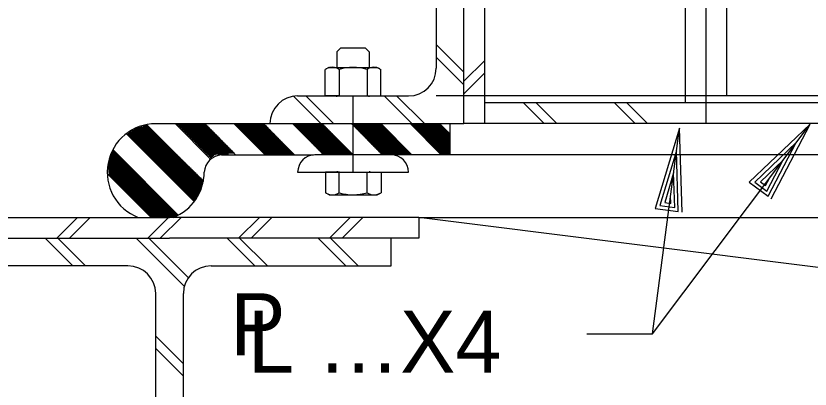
# Model space of a CAD drawing. Extents: x 4.9 to 31.6, y 3.9 to 22.6.
# Drawn here: x 26.163 to 27.357, y 15.318 to 15.879 of the extents above; entities that cross this region are included whole.
import ezdxf

# ---------------------------------------------------------------- set-up
doc = ezdxf.new("R2010")
doc.units = 0
for name, color, linetype in [('Level 2', 7, 'Continuous'), ('Level 25', 7, 'Continuous'), ('Level 3', 7, 'Continuous'), ('Level 50', 7, 'Continuous')]:
    doc.layers.add(name, color=color, linetype=linetype)

msp = doc.modelspace()

# ---------------------------------------------------------------- linework, layer by layer
at = {"layer": 'Level 2'}
for p, q in [((27.2319, 15.7584), (27.2319, 20.9561)), ((26.8364, 15.7168), (26.8364, 17.0205)), ((26.8677, 15.7168), (26.8677, 17.0205)), ((27.1697, 15.748), (27.1697, 16.5655)), ((27.201, 15.7168), (27.201, 16.5655)), ((26.7947, 16.0918), (26.7947, 15.8001)), ((26.6455, 15.8249), (26.6515, 15.8309)), ((26.6515, 15.8309), (26.6879, 15.8309)), ((26.694, 15.8249), (26.6879, 15.8309)), ((26.6455, 15.8249), (26.6455, 15.8014)), ((26.694, 15.8249), (26.694, 15.8014)), ((26.6334, 15.8014), (26.6279, 15.7982)), ((26.6279, 15.7584), (26.6279, 15.7982)), ((26.6334, 15.8014), (26.706, 15.8014)), ((26.6487, 15.7983), (26.6487, 15.7584)), ((26.6907, 15.7983), (26.6907, 15.7584)), ((26.706, 15.8014), (26.7116, 15.7982)), ((26.7116, 15.7584), (26.7116, 15.7982)), ((26.5864, 15.7584), (26.7531, 15.7584)), ((26.6279, 15.7584), (26.7116, 15.7584)), ((26.649, 15.7584), (26.6279, 15.7584)), ((26.6455, 15.7569), (26.6455, 15.7584)), ((26.6697, 15.6438), (26.6697, 15.7584)), ((26.694, 15.7569), (26.694, 15.7584)), ((27.8887, 15.7584), (26.7947, 15.7584)), ((27.409, 15.748), (26.8677, 15.748)), ((26.9573, 15.7168), (26.926, 15.748)), ((26.9761, 15.7168), (26.9449, 15.748)), ((27.094, 15.7168), (27.0627, 15.748)), ((27.1128, 15.7168), (27.0816, 15.748)), ((26.3655, 15.708), (26.3403, 15.708)), ((26.3642, 15.7092), (26.3422, 15.7092)), ((26.3629, 15.7105), (26.3456, 15.7105)), ((26.3617, 15.7117), (26.3499, 15.7117)), ((26.3604, 15.713), (26.3542, 15.713)), ((26.3591, 15.7142), (26.3586, 15.7142)), ((26.4445, 15.6301), (26.3591, 15.7154)), ((26.3729, 15.7168), (26.8156, 15.7168)), ((26.4555, 15.6632), (26.402, 15.7168)), ((26.4479, 15.7161), (26.4045, 15.7161)), ((26.4492, 15.7149), (26.4057, 15.7149)), ((26.4504, 15.7136), (26.407, 15.7136)), ((26.4517, 15.7124), (26.4082, 15.7124)), ((26.4529, 15.7111), (26.4095, 15.7111)), ((26.4542, 15.7099), (26.4107, 15.7099)), ((26.4554, 15.7086), (26.412, 15.7086)), ((26.4931, 15.6699), (26.4462, 15.7168)), ((26.5373, 15.6699), (26.4904, 15.7168)), ((26.5365, 15.7162), (26.4909, 15.7162)), ((26.5377, 15.7149), (26.4922, 15.7149)), ((26.5389, 15.7137), (26.4934, 15.7137)), ((26.5401, 15.7124), (26.4946, 15.7124)), ((26.5413, 15.7112), (26.4959, 15.7112)), ((26.5425, 15.7099), (26.4971, 15.7099)), ((26.5437, 15.7087), (26.4983, 15.7087)), ((26.5814, 15.6699), (26.5346, 15.7168)), ((26.6256, 15.6699), (26.5788, 15.7168)), ((26.6252, 15.715), (26.5806, 15.715)), ((26.6264, 15.7138), (26.5819, 15.7138)), ((26.6277, 15.7125), (26.5831, 15.7125)), ((26.6289, 15.7113), (26.5843, 15.7113)), ((26.6301, 15.71), (26.5855, 15.71)), ((26.6313, 15.7088), (26.5867, 15.7088)), ((26.624, 15.7163), (26.6098, 15.7163)), ((26.6698, 15.6699), (26.623, 15.7168)), ((26.714, 15.6699), (26.6672, 15.7168)), ((26.7122, 15.7155), (26.6681, 15.7155)), ((26.7134, 15.7143), (26.6693, 15.7143)), ((26.7147, 15.713), (26.6705, 15.713)), ((26.7159, 15.7118), (26.6717, 15.7118)), ((26.7172, 15.7105), (26.673, 15.7105)), ((26.7184, 15.7093), (26.6742, 15.7093)), ((26.7197, 15.708), (26.6754, 15.708)), ((26.7582, 15.6699), (26.7113, 15.7168)), ((26.8024, 15.6699), (26.7556, 15.7168)), ((26.8008, 15.7152), (26.7573, 15.7152)), ((26.8022, 15.714), (26.7586, 15.714)), ((26.8035, 15.7127), (26.7598, 15.7127)), ((26.8049, 15.7115), (26.7611, 15.7115)), ((26.8063, 15.7102), (26.7623, 15.7102)), ((26.8077, 15.709), (26.7636, 15.709)), ((26.8156, 15.7009), (26.7997, 15.7168)), ((26.8156, 15.6699), (26.8156, 15.7168)), ((26.8156, 15.7168), (26.8364, 15.7168)), ((27.201, 15.7168), (26.8364, 15.7168)), ((27.409, 15.7168), (27.201, 15.7168)), ((26.4308, 15.5996), (26.3286, 15.7018)), ((26.3719, 15.7017), (26.331, 15.7017)), ((26.3732, 15.7005), (26.3312, 15.7005)), ((26.3745, 15.6992), (26.3324, 15.6992)), ((26.3707, 15.703), (26.3329, 15.703)), ((26.3758, 15.698), (26.3337, 15.698)), ((26.3694, 15.7042), (26.3347, 15.7042)), ((26.3771, 15.6967), (26.3349, 15.6967)), ((26.3681, 15.7055), (26.3366, 15.7055)), ((26.3668, 15.7067), (26.3384, 15.7067)), ((26.4566, 15.7074), (26.4132, 15.7074)), ((26.4579, 15.7061), (26.4145, 15.7061)), ((26.4591, 15.7049), (26.4157, 15.7049)), ((26.4604, 15.7036), (26.417, 15.7036)), ((26.4616, 15.7024), (26.4183, 15.7024)), ((26.4629, 15.7011), (26.4195, 15.7011)), ((26.4641, 15.6999), (26.4208, 15.6999)), ((26.4653, 15.6986), (26.422, 15.6986)), ((26.4666, 15.6974), (26.4233, 15.6974)), ((26.4678, 15.6961), (26.4245, 15.6961)), ((26.5449, 15.7074), (26.4996, 15.7074)), ((26.5461, 15.7062), (26.5008, 15.7062)), ((26.5473, 15.7049), (26.5021, 15.7049)), ((26.5485, 15.7037), (26.5033, 15.7037)), ((26.5497, 15.7024), (26.5045, 15.7024)), ((26.5509, 15.7012), (26.5058, 15.7012)), ((26.5521, 15.6999), (26.507, 15.6999)), ((26.5533, 15.6987), (26.5082, 15.6987)), ((26.5545, 15.6974), (26.5095, 15.6974)), ((26.5557, 15.6962), (26.5107, 15.6962)), ((26.6325, 15.7075), (26.5879, 15.7075)), ((26.6337, 15.7063), (26.5892, 15.7063)), ((26.6349, 15.705), (26.5904, 15.705)), ((26.6362, 15.7038), (26.5916, 15.7038)), ((26.6374, 15.7025), (26.5928, 15.7025)), ((26.6386, 15.7013), (26.594, 15.7013)), ((26.6398, 15.7), (26.5952, 15.7)), ((26.641, 15.6988), (26.5965, 15.6988)), ((26.6422, 15.6975), (26.5977, 15.6975)), ((26.6434, 15.6963), (26.5989, 15.6963)), ((26.7209, 15.7068), (26.6767, 15.7068)), ((26.7222, 15.7055), (26.6779, 15.7055)), ((26.7234, 15.7043), (26.6791, 15.7043)), ((26.7247, 15.703), (26.6804, 15.703)), ((26.726, 15.7018), (26.6816, 15.7018)), ((26.7272, 15.7005), (26.6828, 15.7005)), ((26.7285, 15.6993), (26.6841, 15.6993)), ((26.7297, 15.698), (26.6853, 15.698)), ((26.731, 15.6968), (26.6865, 15.6968)), ((26.809, 15.7077), (26.7648, 15.7077)), ((26.8104, 15.7065), (26.7661, 15.7065)), ((26.8118, 15.7052), (26.7673, 15.7052)), ((26.8132, 15.704), (26.7686, 15.704)), ((26.8145, 15.7027), (26.7698, 15.7027)), ((26.8153, 15.7015), (26.7711, 15.7015)), ((26.8153, 15.7002), (26.7723, 15.7002)), ((26.8153, 15.699), (26.7736, 15.699)), ((26.8154, 15.6977), (26.7748, 15.6977)), ((26.8154, 15.6965), (26.7761, 15.6965)), ((26.3784, 15.6955), (26.3362, 15.6955)), ((26.3797, 15.6942), (26.3374, 15.6942)), ((26.381, 15.693), (26.3387, 15.693)), ((26.3823, 15.6917), (26.3399, 15.6917)), ((26.3836, 15.6905), (26.3412, 15.6905)), ((26.3849, 15.6892), (26.3424, 15.6892)), ((26.3862, 15.688), (26.3437, 15.688)), ((26.3874, 15.6867), (26.3449, 15.6867)), ((26.3887, 15.6855), (26.3462, 15.6855)), ((26.39, 15.6842), (26.3474, 15.6842)), ((26.4691, 15.6949), (26.4258, 15.6949)), ((26.4703, 15.6936), (26.427, 15.6936)), ((26.4716, 15.6924), (26.4283, 15.6924)), ((26.4728, 15.6911), (26.4295, 15.6911)), ((26.4741, 15.6899), (26.4308, 15.6899)), ((26.4753, 15.6886), (26.432, 15.6886)), ((26.4765, 15.6874), (26.4333, 15.6874)), ((26.4778, 15.6861), (26.4345, 15.6861)), ((26.479, 15.6849), (26.4358, 15.6849)), ((26.5569, 15.6949), (26.512, 15.6949)), ((26.5581, 15.6937), (26.5132, 15.6937)), ((26.5593, 15.6924), (26.5144, 15.6924)), ((26.5605, 15.6912), (26.5157, 15.6912)), ((26.5617, 15.6899), (26.5169, 15.6899)), ((26.5629, 15.6887), (26.5182, 15.6887)), ((26.5641, 15.6874), (26.5194, 15.6874)), ((26.5653, 15.6862), (26.5207, 15.6862)), ((26.5665, 15.6849), (26.5219, 15.6849)), ((26.6447, 15.695), (26.6001, 15.695)), ((26.6459, 15.6938), (26.6013, 15.6938)), ((26.6471, 15.6925), (26.6026, 15.6925)), ((26.6483, 15.6913), (26.6038, 15.6913)), ((26.6495, 15.69), (26.605, 15.69)), ((26.6507, 15.6888), (26.6062, 15.6888)), ((26.6519, 15.6875), (26.6074, 15.6875)), ((26.6532, 15.6863), (26.6087, 15.6863)), ((26.6544, 15.685), (26.6099, 15.685)), ((26.7323, 15.6955), (26.6878, 15.6955)), ((26.7335, 15.6943), (26.689, 15.6943)), ((26.7348, 15.693), (26.6902, 15.693)), ((26.736, 15.6918), (26.6915, 15.6918)), ((26.7373, 15.6905), (26.6927, 15.6905)), ((26.7386, 15.6893), (26.6939, 15.6893)), ((26.7398, 15.688), (26.6952, 15.688)), ((26.7411, 15.6868), (26.6964, 15.6868)), ((26.7423, 15.6855), (26.6976, 15.6855)), ((26.7436, 15.6843), (26.6989, 15.6843)), ((26.8154, 15.6952), (26.7773, 15.6952)), ((26.8154, 15.694), (26.7786, 15.694)), ((26.8154, 15.6927), (26.7798, 15.6927)), ((26.8155, 15.6915), (26.7811, 15.6915)), ((26.8155, 15.6902), (26.7823, 15.6902)), ((26.8155, 15.689), (26.7836, 15.689)), ((26.8155, 15.6877), (26.7848, 15.6877)), ((26.8156, 15.6865), (26.7861, 15.6865)), ((26.8156, 15.6852), (26.7873, 15.6852)), ((26.8156, 15.684), (26.7886, 15.684)), ((26.3129, 15.6724), (26.3071, 15.6724)), ((26.3116, 15.6736), (26.3077, 15.6736)), ((26.4068, 15.5793), (26.3083, 15.6778)), ((26.3103, 15.6749), (26.3084, 15.6749)), ((26.3913, 15.683), (26.3487, 15.683)), ((26.3926, 15.6817), (26.3499, 15.6817)), ((26.3939, 15.6805), (26.3511, 15.6805)), ((26.3952, 15.6792), (26.3524, 15.6792)), ((26.3964, 15.678), (26.3536, 15.678)), ((26.3977, 15.6767), (26.3549, 15.6767)), ((26.399, 15.6755), (26.3561, 15.6755)), ((26.4003, 15.6742), (26.3574, 15.6742)), ((26.4016, 15.673), (26.3586, 15.673)), ((26.4803, 15.6836), (26.437, 15.6836)), ((26.4815, 15.6824), (26.4383, 15.6824)), ((26.4828, 15.6811), (26.4395, 15.6811)), ((26.484, 15.6799), (26.4408, 15.6799)), ((26.4852, 15.6786), (26.442, 15.6786)), ((26.4865, 15.6774), (26.4433, 15.6774)), ((26.4877, 15.6761), (26.4445, 15.6761)), ((26.489, 15.6749), (26.4458, 15.6749)), ((26.4902, 15.6736), (26.447, 15.6736)), ((26.4915, 15.6724), (26.4483, 15.6724)), ((26.5677, 15.6837), (26.5231, 15.6837)), ((26.5689, 15.6824), (26.5244, 15.6824)), ((26.5701, 15.6812), (26.5256, 15.6812)), ((26.5713, 15.6799), (26.5268, 15.6799)), ((26.5725, 15.6787), (26.5281, 15.6787)), ((26.5737, 15.6774), (26.5293, 15.6774)), ((26.5749, 15.6762), (26.5306, 15.6762)), ((26.5761, 15.6749), (26.5318, 15.6749)), ((26.5773, 15.6737), (26.533, 15.6737)), ((26.5785, 15.6724), (26.5343, 15.6724)), ((26.6556, 15.6838), (26.6111, 15.6838)), ((26.6568, 15.6825), (26.6123, 15.6825)), ((26.658, 15.6813), (26.6135, 15.6813)), ((26.6592, 15.68), (26.6147, 15.68)), ((26.6604, 15.6788), (26.6159, 15.6788)), ((26.6617, 15.6775), (26.6172, 15.6775)), ((26.6629, 15.6763), (26.6184, 15.6763)), ((26.6641, 15.675), (26.6196, 15.675)), ((26.6653, 15.6738), (26.6208, 15.6738)), ((26.6665, 15.6725), (26.622, 15.6725)), ((26.7448, 15.683), (26.7001, 15.683)), ((26.7461, 15.6818), (26.7013, 15.6818)), ((26.7474, 15.6805), (26.7026, 15.6805)), ((26.7486, 15.6793), (26.7038, 15.6793)), ((26.7499, 15.678), (26.705, 15.678)), ((26.7511, 15.6768), (26.7063, 15.6768)), ((26.7524, 15.6755), (26.7075, 15.6755)), ((26.7537, 15.6743), (26.7087, 15.6743)), ((26.7549, 15.673), (26.7099, 15.673)), ((26.8156, 15.6827), (26.7898, 15.6827)), ((26.8157, 15.6815), (26.7911, 15.6815)), ((26.8157, 15.6802), (26.7923, 15.6802)), ((26.8157, 15.679), (26.7936, 15.679)), ((26.8157, 15.6777), (26.7948, 15.6777)), ((26.8157, 15.6765), (26.7961, 15.6765)), ((26.8157, 15.6752), (26.7974, 15.6752)), ((26.8158, 15.674), (26.7986, 15.674)), ((26.8158, 15.6727), (26.7999, 15.6727)), ((26.3242, 15.6611), (26.3028, 15.6611)), ((26.3229, 15.6624), (26.303, 15.6624)), ((26.3217, 15.6636), (26.3033, 15.6636)), ((26.3204, 15.6649), (26.3036, 15.6649)), ((26.3192, 15.6661), (26.3038, 15.6661)), ((26.3179, 15.6674), (26.3043, 15.6674)), ((26.3167, 15.6686), (26.305, 15.6686)), ((26.3154, 15.6699), (26.3057, 15.6699)), ((26.3141, 15.6711), (26.3064, 15.6711)), ((26.4029, 15.6717), (26.3599, 15.6717)), ((26.4042, 15.6705), (26.3611, 15.6705)), ((26.4055, 15.6692), (26.3624, 15.6692)), ((26.4068, 15.668), (26.3636, 15.668)), ((26.4081, 15.6667), (26.3649, 15.6667)), ((26.4093, 15.6655), (26.3661, 15.6655)), ((26.4106, 15.6642), (26.3674, 15.6642)), ((26.4119, 15.663), (26.3686, 15.663)), ((26.4132, 15.6617), (26.3698, 15.6617)), ((26.4145, 15.6605), (26.3711, 15.6605)), ((26.4824, 15.6711), (26.4495, 15.6711)), ((26.4629, 15.6699), (26.4508, 15.6699)), ((26.4603, 15.6686), (26.4521, 15.6686)), ((26.4587, 15.6674), (26.4533, 15.6674)), ((26.4572, 15.6661), (26.4546, 15.6661)), ((26.4721, 15.6699), (26.6103, 15.6699)), ((26.5797, 15.6712), (26.5355, 15.6712)), ((26.5521, 15.6699), (26.5367, 15.6699)), ((26.8156, 15.6699), (26.6124, 15.6699)), ((26.6677, 15.6713), (26.6233, 15.6713)), ((26.6689, 15.67), (26.6245, 15.67)), ((26.7562, 15.6718), (26.7112, 15.6718)), ((26.7574, 15.6705), (26.7124, 15.6705)), ((26.8158, 15.6715), (26.8011, 15.6715)), ((27.4822, 15.6699), (26.8156, 15.6699)), ((26.333, 15.6524), (26.3011, 15.6524)), ((26.3318, 15.6536), (26.3012, 15.6536)), ((26.3343, 15.6511), (26.3012, 15.6511)), ((26.3355, 15.6499), (26.3014, 15.6499)), ((26.3305, 15.6549), (26.3015, 15.6549)), ((26.3368, 15.6486), (26.3015, 15.6486)), ((26.3292, 15.6561), (26.3017, 15.6561)), ((26.328, 15.6574), (26.302, 15.6574)), ((26.3267, 15.6586), (26.3023, 15.6586)), ((26.3255, 15.6599), (26.3025, 15.6599)), ((26.4158, 15.6592), (26.3723, 15.6592)), ((26.4171, 15.658), (26.3736, 15.658)), ((26.4184, 15.6567), (26.3748, 15.6567)), ((26.4197, 15.6555), (26.3761, 15.6555)), ((26.4209, 15.6542), (26.3773, 15.6542)), ((26.4222, 15.653), (26.3786, 15.653)), ((26.4235, 15.6517), (26.3798, 15.6517)), ((26.4248, 15.6505), (26.3811, 15.6505)), ((26.4261, 15.6492), (26.3823, 15.6492)), ((26.3661, 15.5759), (26.2999, 15.642)), ((26.3381, 15.6474), (26.3017, 15.6474)), ((26.3393, 15.6461), (26.3018, 15.6461)), ((26.3406, 15.6449), (26.3019, 15.6449)), ((26.3418, 15.6436), (26.3021, 15.6436)), ((26.3431, 15.6424), (26.3022, 15.6424)), ((26.3444, 15.6411), (26.3024, 15.6411)), ((26.3456, 15.6399), (26.3025, 15.6399)), ((26.3469, 15.6386), (26.3037, 15.6386)), ((26.3482, 15.6374), (26.3049, 15.6374)), ((26.3494, 15.6361), (26.3062, 15.6361)), ((26.4274, 15.648), (26.3836, 15.648)), ((26.4287, 15.6467), (26.3848, 15.6467)), ((26.43, 15.6455), (26.3861, 15.6455)), ((26.4313, 15.6442), (26.3873, 15.6442)), ((26.4326, 15.643), (26.3886, 15.643)), ((26.4338, 15.6417), (26.3898, 15.6417)), ((26.4351, 15.6405), (26.3911, 15.6405)), ((26.4364, 15.6392), (26.3923, 15.6392)), ((26.4377, 15.638), (26.3935, 15.638)), ((26.439, 15.6367), (26.3948, 15.6367)), ((26.5864, 15.6438), (26.7531, 15.6438)), ((26.5864, 15.6438), (26.6207, 15.6438)), ((26.6281, 15.6437), (26.7118, 15.6437)), ((26.6493, 15.6437), (26.6281, 15.6437)), ((26.6281, 15.6437), (26.6281, 15.613)), ((26.6457, 15.6452), (26.6457, 15.6437)), ((26.649, 15.6129), (26.649, 15.6437)), ((26.6909, 15.6129), (26.6909, 15.6437)), ((26.6942, 15.6452), (26.6942, 15.6437)), ((26.7118, 15.6437), (26.7118, 15.613)), ((26.3507, 15.6349), (26.3074, 15.6349)), ((26.3519, 15.6336), (26.3087, 15.6336)), ((26.3532, 15.6324), (26.3099, 15.6324)), ((26.3544, 15.6311), (26.3112, 15.6311)), ((26.3557, 15.6299), (26.3124, 15.6299)), ((26.357, 15.6286), (26.3137, 15.6286)), ((26.3582, 15.6274), (26.315, 15.6274)), ((26.3595, 15.6261), (26.3162, 15.6261)), ((26.3607, 15.6249), (26.3175, 15.6249)), ((26.4403, 15.6355), (26.396, 15.6355)), ((26.4416, 15.6342), (26.3973, 15.6342)), ((26.4429, 15.633), (26.3985, 15.633)), ((26.4442, 15.6317), (26.3998, 15.6317)), ((26.4454, 15.6305), (26.401, 15.6305)), ((26.4449, 15.6292), (26.4023, 15.6292)), ((26.4445, 15.628), (26.4035, 15.628)), ((26.444, 15.6267), (26.4048, 15.6267)), ((26.4435, 15.6255), (26.406, 15.6255)), ((26.443, 15.6242), (26.4073, 15.6242)), ((26.362, 15.6236), (26.3187, 15.6236)), ((26.3633, 15.6224), (26.32, 15.6224)), ((26.3645, 15.6211), (26.3213, 15.6211)), ((26.3658, 15.6199), (26.3225, 15.6199)), ((26.3671, 15.6186), (26.3238, 15.6186)), ((26.3683, 15.6174), (26.325, 15.6174)), ((26.3696, 15.6161), (26.3263, 15.6161)), ((26.3708, 15.6149), (26.3276, 15.6149)), ((26.3721, 15.6136), (26.3288, 15.6136)), ((26.3734, 15.6124), (26.3301, 15.6124)), ((26.4425, 15.623), (26.4085, 15.623)), ((26.442, 15.6217), (26.4098, 15.6217)), ((26.4415, 15.6205), (26.411, 15.6205)), ((26.441, 15.6192), (26.4122, 15.6192)), ((26.4405, 15.618), (26.4135, 15.618)), ((26.44, 15.6167), (26.4147, 15.6167)), ((26.4395, 15.6155), (26.416, 15.6155)), ((26.4388, 15.6142), (26.4172, 15.6142)), ((26.4381, 15.613), (26.4185, 15.613)), ((26.6337, 15.6097), (26.6281, 15.613)), ((26.7062, 15.6097), (26.7118, 15.613)), ((26.3746, 15.6111), (26.3313, 15.6111)), ((26.3759, 15.6099), (26.3326, 15.6099)), ((26.3771, 15.6086), (26.3338, 15.6086)), ((26.3784, 15.6074), (26.3351, 15.6074)), ((26.3797, 15.6061), (26.3364, 15.6061)), ((26.3809, 15.6049), (26.3376, 15.6049)), ((26.3822, 15.6036), (26.3389, 15.6036)), ((26.3834, 15.6024), (26.3401, 15.6024)), ((26.3847, 15.6011), (26.3414, 15.6011)), ((26.4373, 15.6117), (26.4197, 15.6117)), ((26.4366, 15.6105), (26.421, 15.6105)), ((26.4358, 15.6092), (26.4222, 15.6092)), ((26.4351, 15.608), (26.4235, 15.608)), ((26.4344, 15.6067), (26.4247, 15.6067)), ((26.4336, 15.6055), (26.426, 15.6055)), ((26.4329, 15.6042), (26.4272, 15.6042)), ((26.4322, 15.603), (26.4285, 15.603)), ((26.4314, 15.6017), (26.4297, 15.6017)), ((26.6337, 15.6097), (26.7062, 15.6097)), ((26.3859, 15.5999), (26.3427, 15.5999)), ((26.3872, 15.5986), (26.3439, 15.5986)), ((26.3885, 15.5974), (26.3452, 15.5974)), ((26.3897, 15.5961), (26.3464, 15.5961)), ((26.3909, 15.5944), (26.3476, 15.5944)), ((26.3922, 15.5932), (26.3489, 15.5932)), ((26.3934, 15.5919), (26.3501, 15.5919)), ((26.3947, 15.5907), (26.3514, 15.5907)), ((26.3959, 15.5894), (26.3526, 15.5894)), ((26.3972, 15.5882), (26.3539, 15.5882)), ((26.3985, 15.5869), (26.3552, 15.5869)), ((26.3997, 15.5857), (26.3564, 15.5857)), ((26.401, 15.5844), (26.3577, 15.5844)), ((26.4022, 15.5832), (26.3589, 15.5832)), ((26.4035, 15.5819), (26.3602, 15.5819)), ((26.4048, 15.5807), (26.3614, 15.5807)), ((26.4053, 15.5794), (26.3627, 15.5794)), ((26.403, 15.5782), (26.3639, 15.5782)), ((26.402, 15.577), (26.3649, 15.577)), ((26.0187, 15.5759), (26.3937, 15.5759)), ((26.2242, 15.5446), (26.2554, 15.5759)), ((26.243, 15.5446), (26.2743, 15.5759)), ((26.3609, 15.5446), (26.3921, 15.5759)), ((26.3797, 15.5446), (26.411, 15.5759)), ((26.7687, 15.5759), (26.3937, 15.5759)), ((26.4976, 15.5446), (26.5288, 15.5759)), ((26.5164, 15.5446), (26.5477, 15.5759)), ((26.6343, 15.5446), (26.6656, 15.5759)), ((26.6532, 15.5446), (26.6844, 15.5759)), ((26.7687, 15.5759), (26.7687, 15.5446)), ((26.7687, 15.5759), (27.4822, 15.5759)), ((27.4302, 15.4926), (26.7687, 15.5759)), ((26.0187, 15.5446), (26.3937, 15.5446)), ((26.2485, 15.503), (26.2068, 15.5446)), ((26.2674, 15.503), (26.2257, 15.5446)), ((26.416, 15.4722), (26.3436, 15.5446)), ((26.422, 15.4851), (26.3624, 15.5446)), ((26.7687, 15.5446), (26.3937, 15.5446)), ((26.5219, 15.503), (26.4803, 15.5446)), ((26.5408, 15.503), (26.4991, 15.5446)), ((26.6586, 15.503), (26.617, 15.5446)), ((26.6775, 15.503), (26.6358, 15.5446)), ((26.727, 15.503), (26.727, 15.5446)), ((26.3312, 15.503), (26.0604, 15.503)), ((26.4562, 15.503), (26.727, 15.503)), ((26.3729, 15.1044), (26.3729, 15.4613)), ((26.4145, 15.1044), (26.4145, 15.4613)), ((26.4145, 15.3558), (26.3729, 15.3975)), ((26.4145, 15.337), (26.3729, 15.3786))]:
    msp.add_line(p, q, dxfattribs=at)
for centre, radius, start, end in [((26.6385, 15.7833), 0.0182, 55.489, 120.2876), ((26.6695, 15.7287), 0.0727, 73.0184, 106.4966), ((26.701, 15.7833), 0.0182, 59.7124, 124.511), ((26.7531, 15.8001), 0.0417, 270, 0), ((26.5864, 15.7168), 0.0417, 90, 180), ((26.3729, 15.6438), 0.0729, 90, 248.7036), ((26.4736, 15.642), 0.0279, 93.1528, 176.2998), ((26.6124, 15.6438), 0.026, 90, 180), ((26.727, 15.6438), 0.026, 0, 90), ((26.3729, 15.6438), 0.0729, 291.2964, 0), ((26.6387, 15.6279), 0.0182, 239.7124, 304.511), ((26.6697, 15.6825), 0.0727, 253.5034, 286.9816), ((26.7012, 15.6279), 0.0182, 235.489, 300.2876), ((26.3312, 15.4613), 0.0417, 0, 90), ((26.4562, 15.4613), 0.0417, 90, 180)]:
    msp.add_arc(centre, radius, start, end, dxfattribs=at)
at = {"layer": 'Level 25'}
msp.add_line((27.1201, 15.4008), (27.357, 15.716), dxfattribs=at)
at = {"layer": 'Level 3'}
for p, q in [((26.8364, 15.7941), (26.7947, 15.8357)), ((26.8364, 15.7752), (26.7947, 15.8169)), ((26.8364, 15.7805), (26.8677, 15.8118)), ((26.8364, 15.7617), (26.8677, 15.7929)), ((26.6214, 15.7168), (26.5798, 15.7584)), ((26.6403, 15.7168), (26.5986, 15.7584)), ((26.7581, 15.7168), (26.7165, 15.7584)), ((26.777, 15.7168), (26.7353, 15.7584))]:
    msp.add_line(p, q, dxfattribs=at)
msp.add_lwpolyline([(27.0215, 15.4008), (27.1201, 15.4008), (27.1606, 15.7102)], dxfattribs=at)
at = {"layer": 'Level 50'}
for p, q in [((27.1606, 15.7102), (27.1606, 15.7102)), ((27.357, 15.716), (27.357, 15.716)), ((27.3362, 15.6883), (27.3362, 15.6883)), ((27.1561, 15.6758), (27.1561, 15.6758))]:
    msp.add_line(p, q, dxfattribs=at)
for points in [[(27.1649, 15.5839), (27.1606, 15.7102), (27.1239, 15.5893), (27.1589, 15.5847), (27.1561, 15.6758), (27.1312, 15.5937), (27.1537, 15.5908), (27.1518, 15.6428), (27.1385, 15.5981), (27.1478, 15.5969), (27.1473, 15.6084)], [(27.2986, 15.6039), (27.357, 15.716), (27.2656, 15.6288), (27.2938, 15.6075), (27.3362, 15.6883), (27.2741, 15.629), (27.2922, 15.6154), (27.3161, 15.6616), (27.2826, 15.6293), (27.2901, 15.6237), (27.2953, 15.6339)]]:
    msp.add_lwpolyline(points, dxfattribs=at)

# ---------------------------------------------------------------- texts
at = {"layer": 'Level 25'}
for s, height, p in [('P', 0.0933, (26.4849, 15.3684)), ('L …X4', 0.09329, (26.5117, 15.3422))]:
    msp.add_text(s, height=height, dxfattribs=at).set_placement(p)

doc.saveas('drawing.dxf')
